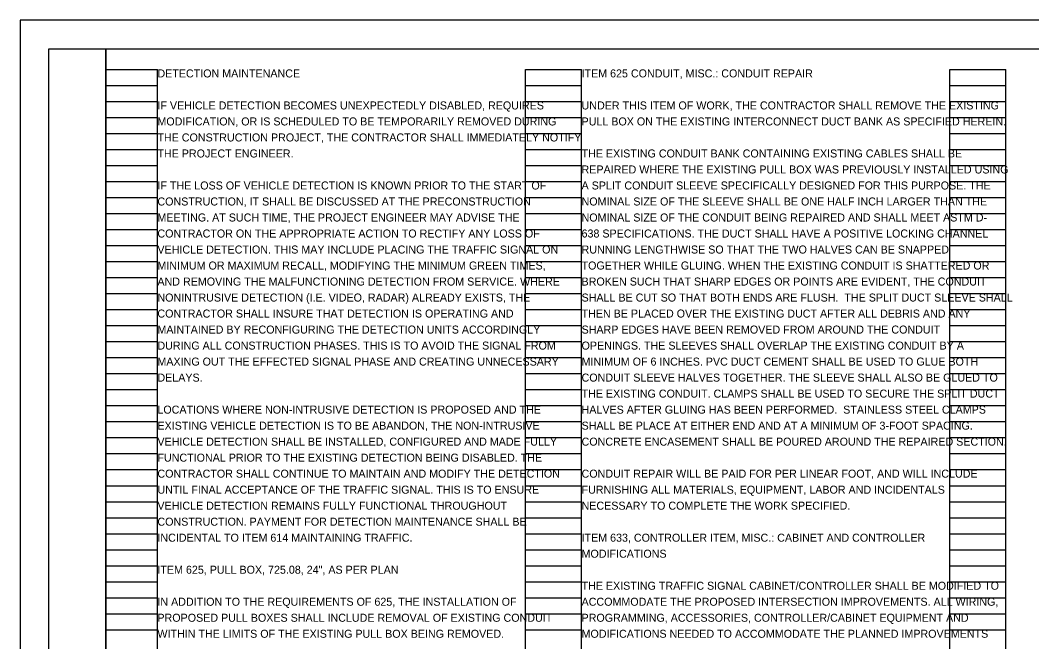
# Model space of a CAD drawing. Extents: x 0 to 34, y 0 to 22.
# Drawn here: x 0 to 17.7, y 11.13 to 22 of the extents above; entities that cross this region are included whole.
import ezdxf

# ---------------------------------------------------------------- set-up
doc = ezdxf.new("R2010")
doc.units = 0
for name, color, linetype in [('SH_Border', 7, 'Continuous'), ('SH_Cut_Line', 7, 'Continuous'), ('SH_Data', 7, 'Continuous'), ('SH_Text', 7, 'Continuous')]:
    doc.layers.add(name, color=color, linetype=linetype)

msp = doc.modelspace()

# ---------------------------------------------------------------- linework, layer by layer
at = {"layer": 'SH_Border'}
for points in [[(0.5, 21.5), (1.5, 21.5), (1.5, 0.5), (0.5, 0.5)], [(1.5, 21.5), (33.5, 21.5), (33.5, 0.5), (1.5, 0.5)]]:
    msp.add_lwpolyline(points, close=True, dxfattribs=at)
at = {"layer": 'SH_Cut_Line'}
msp.add_lwpolyline([(0, 0), (34, 0), (34, 22), (0, 22)], close=True, dxfattribs=at)
at = {"layer": 'SH_Data'}
for p, q in [((1.5, 0.98), (1.5, 21.14)), ((1.5, 21.14), (2.4, 21.14)), ((2.4, 0.98), (2.4, 21.14)), ((8.84, 0.98), (8.84, 21.14)), ((8.84, 21.14), (9.82, 21.14)), ((9.82, 0.98), (9.82, 21.14)), ((16.26, 0.98), (16.26, 21.14)), ((16.26, 21.14), (17.24, 21.14)), ((17.24, 0.98), (17.24, 21.14)), ((1.5, 20.86), (2.4, 20.86)), ((8.84, 20.86), (9.82, 20.86)), ((16.26, 20.86), (17.24, 20.86)), ((1.5, 20.58), (2.4, 20.58)), ((8.84, 20.58), (9.82, 20.58)), ((16.26, 20.58), (17.24, 20.58)), ((1.5, 20.3), (2.4, 20.3)), ((8.84, 20.3), (9.82, 20.3)), ((16.26, 20.3), (17.24, 20.3)), ((1.5, 20.02), (2.4, 20.02)), ((8.84, 20.02), (9.82, 20.02)), ((16.26, 20.02), (17.24, 20.02)), ((1.5, 19.74), (2.4, 19.74)), ((8.84, 19.74), (9.82, 19.74)), ((16.26, 19.74), (17.24, 19.74)), ((1.5, 19.46), (2.4, 19.46)), ((8.84, 19.46), (9.82, 19.46)), ((16.26, 19.46), (17.24, 19.46)), ((1.5, 19.18), (2.4, 19.18)), ((8.84, 19.18), (9.82, 19.18)), ((16.26, 19.18), (17.24, 19.18)), ((1.5, 18.9), (2.4, 18.9)), ((8.84, 18.9), (9.82, 18.9)), ((16.26, 18.9), (17.24, 18.9)), ((1.5, 18.62), (2.4, 18.62)), ((8.84, 18.62), (9.82, 18.62)), ((16.26, 18.62), (17.24, 18.62)), ((1.5, 18.34), (2.4, 18.34)), ((8.84, 18.34), (9.82, 18.34)), ((16.26, 18.34), (17.24, 18.34)), ((1.5, 18.06), (2.4, 18.06)), ((8.84, 18.06), (9.82, 18.06)), ((16.26, 18.06), (17.24, 18.06)), ((1.5, 17.78), (2.4, 17.78)), ((8.84, 17.78), (9.82, 17.78)), ((16.26, 17.78), (17.24, 17.78)), ((1.5, 17.5), (2.4, 17.5)), ((8.84, 17.5), (9.82, 17.5)), ((16.26, 17.5), (17.24, 17.5)), ((1.5, 17.22), (2.4, 17.22)), ((8.84, 17.22), (9.82, 17.22)), ((16.26, 17.22), (17.24, 17.22)), ((1.5, 16.94), (2.4, 16.94)), ((8.84, 16.94), (9.82, 16.94)), ((16.26, 16.94), (17.24, 16.94)), ((1.5, 16.66), (2.4, 16.66)), ((8.84, 16.66), (9.82, 16.66)), ((16.26, 16.66), (17.24, 16.66)), ((1.5, 16.38), (2.4, 16.38)), ((8.84, 16.38), (9.82, 16.38)), ((16.26, 16.38), (17.24, 16.38)), ((1.5, 16.1), (2.4, 16.1)), ((8.84, 16.1), (9.82, 16.1)), ((16.26, 16.1), (17.24, 16.1)), ((1.5, 15.82), (2.4, 15.82)), ((8.84, 15.82), (9.82, 15.82)), ((16.26, 15.82), (17.24, 15.82)), ((1.5, 15.54), (2.4, 15.54)), ((8.84, 15.54), (9.82, 15.54)), ((16.26, 15.54), (17.24, 15.54)), ((1.5, 15.26), (2.4, 15.26)), ((8.84, 15.26), (9.82, 15.26)), ((16.26, 15.26), (17.24, 15.26)), ((1.5, 14.98), (2.4, 14.98)), ((8.84, 14.98), (9.82, 14.98)), ((16.26, 14.98), (17.24, 14.98)), ((1.5, 14.7), (2.4, 14.7)), ((8.84, 14.7), (9.82, 14.7)), ((16.26, 14.7), (17.24, 14.7)), ((1.5, 14.42), (2.4, 14.42)), ((8.84, 14.42), (9.82, 14.42)), ((16.26, 14.42), (17.24, 14.42)), ((1.5, 14.14), (2.4, 14.14)), ((8.84, 14.14), (9.82, 14.14)), ((16.26, 14.14), (17.24, 14.14)), ((1.5, 13.86), (2.4, 13.86)), ((8.84, 13.86), (9.82, 13.86)), ((16.26, 13.86), (17.24, 13.86)), ((1.5, 13.58), (2.4, 13.58)), ((8.84, 13.58), (9.82, 13.58)), ((16.26, 13.58), (17.24, 13.58)), ((1.5, 13.3), (2.4, 13.3)), ((8.84, 13.3), (9.82, 13.3)), ((16.26, 13.3), (17.24, 13.3)), ((1.5, 13.02), (2.4, 13.02)), ((8.84, 13.02), (9.82, 13.02)), ((16.26, 13.02), (17.24, 13.02)), ((1.5, 12.74), (2.4, 12.74)), ((8.84, 12.74), (9.82, 12.74)), ((16.26, 12.74), (17.24, 12.74)), ((1.5, 12.46), (2.4, 12.46)), ((8.84, 12.46), (9.82, 12.46)), ((16.26, 12.46), (17.24, 12.46)), ((1.5, 12.18), (2.4, 12.18)), ((8.84, 12.18), (9.82, 12.18)), ((16.26, 12.18), (17.24, 12.18)), ((1.5, 11.9), (2.4, 11.9)), ((8.84, 11.9), (9.82, 11.9)), ((16.26, 11.9), (17.24, 11.9)), ((1.5, 11.62), (2.4, 11.62)), ((8.84, 11.62), (9.82, 11.62)), ((16.26, 11.62), (17.24, 11.62)), ((1.5, 11.34), (2.4, 11.34)), ((8.84, 11.34), (9.82, 11.34)), ((16.26, 11.34), (17.24, 11.34))]:
    msp.add_line(p, q, dxfattribs=at)

# ---------------------------------------------------------------- texts
at = {"layer": 'SH_Text'}
for s, p in [('DETECTION MAINTENANCE', (2.4, 21)), ('ITEM 625 CONDUIT, MISC.: CONDUIT REPAIR', (9.82, 21)), ('IF VEHICLE DETECTION BECOMES UNEXPECTEDLY DISABLED, REQUIRES ', (2.4, 20.44)), ('UNDER THIS ITEM OF WORK, THE CONTRACTOR SHALL REMOVE THE EXISTING ', (9.82, 20.44)), ('MODIFICATION, OR IS SCHEDULED TO BE TEMPORARILY REMOVED DURING ', (2.4, 20.16)), ('PULL BOX ON THE EXISTING INTERCONNECT DUCT BANK AS SPECIFIED HEREIN.', (9.82, 20.16)), ('THE CONSTRUCTION PROJECT, THE CONTRACTOR SHALL IMMEDIATELY NOTIFY ', (2.4, 19.88)), ('THE PROJECT ENGINEER.', (2.4, 19.6)), ('THE EXISTING CONDUIT BANK CONTAINING EXISTING CABLES SHALL BE ', (9.82, 19.6)), ('REPAIRED WHERE THE EXISTING PULL BOX WAS PREVIOUSLY INSTALLED USING ', (9.82, 19.32)), ('IF THE LOSS OF VEHICLE DETECTION IS KNOWN PRIOR TO THE START OF ', (2.4, 19.04)), ('A SPLIT CONDUIT SLEEVE SPECIFICALLY DESIGNED FOR THIS PURPOSE. THE ', (9.82, 19.04)), ('CONSTRUCTION, IT SHALL BE DISCUSSED AT THE PRECONSTRUCTION ', (2.4, 18.76)), ('NOMINAL SIZE OF THE SLEEVE SHALL BE ONE HALF INCH LARGER THAN THE ', (9.82, 18.76)), ('MEETING. AT SUCH TIME, THE PROJECT ENGINEER MAY ADVISE THE ', (2.4, 18.48)), ('NOMINAL SIZE OF THE CONDUIT BEING REPAIRED AND SHALL MEET ASTM D-', (9.82, 18.48)), ('CONTRACTOR ON THE APPROPRIATE ACTION TO RECTIFY ANY LOSS OF ', (2.4, 18.2)), ('638 SPECIFICATIONS. THE DUCT SHALL HAVE A POSITIVE LOCKING CHANNEL ', (9.82, 18.2)), ('VEHICLE DETECTION. THIS MAY INCLUDE PLACING THE TRAFFIC SIGNAL ON ', (2.4, 17.92)), ('RUNNING LENGTHWISE SO THAT THE TWO HALVES CAN BE SNAPPED ', (9.82, 17.92)), ('MINIMUM OR MAXIMUM RECALL, MODIFYING THE MINIMUM GREEN TIMES, ', (2.4, 17.64)), ('TOGETHER WHILE GLUING. WHEN THE EXISTING CONDUIT IS SHATTERED OR ', (9.82, 17.64)), ('AND REMOVING THE MALFUNCTIONING DETECTION FROM SERVICE. WHERE ', (2.4, 17.36)), ('BROKEN SUCH THAT SHARP EDGES OR POINTS ARE EVIDENT, THE CONDUIT ', (9.82, 17.36)), ('NONINTRUSIVE DETECTION (I.E. VIDEO, RADAR) ALREADY EXISTS, THE ', (2.4, 17.08)), ('SHALL BE CUT SO THAT BOTH ENDS ARE FLUSH.  THE SPLIT DUCT SLEEVE SHALL ', (9.82, 17.08)), ('CONTRACTOR SHALL INSURE THAT DETECTION IS OPERATING AND ', (2.4, 16.8)), ('THEN BE PLACED OVER THE EXISTING DUCT AFTER ALL DEBRIS AND ANY ', (9.82, 16.8)), ('MAINTAINED BY RECONFIGURING THE DETECTION UNITS ACCORDINGLY ', (2.4, 16.52)), ('SHARP EDGES HAVE BEEN REMOVED FROM AROUND THE CONDUIT ', (9.82, 16.52)), ('DURING ALL CONSTRUCTION PHASES. THIS IS TO AVOID THE SIGNAL FROM ', (2.4, 16.24)), ('OPENINGS. THE SLEEVES SHALL OVERLAP THE EXISTING CONDUIT BY A ', (9.82, 16.24)), ('MAXING OUT THE EFFECTED SIGNAL PHASE AND CREATING UNNECESSARY ', (2.4, 15.96)), ('MINIMUM OF 6 INCHES. PVC DUCT CEMENT SHALL BE USED TO GLUE BOTH ', (9.82, 15.96)), ('DELAYS.', (2.4, 15.68)), ('CONDUIT SLEEVE HALVES TOGETHER. THE SLEEVE SHALL ALSO BE GLUED TO ', (9.82, 15.68)), ('THE EXISTING CONDUIT. CLAMPS SHALL BE USED TO SECURE THE SPLIT DUCT ', (9.82, 15.4)), ('LOCATIONS WHERE NON-INTRUSIVE DETECTION IS PROPOSED AND THE ', (2.4, 15.12)), ('HALVES AFTER GLUING HAS BEEN PERFORMED.  STAINLESS STEEL CLAMPS ', (9.82, 15.12)), ('EXISTING VEHICLE DETECTION IS TO BE ABANDON, THE NON-INTRUSIVE ', (2.4, 14.84)), ('SHALL BE PLACE AT EITHER END AND AT A MINIMUM OF 3-FOOT SPACING. ', (9.82, 14.84)), ('VEHICLE DETECTION SHALL BE INSTALLED, CONFIGURED AND MADE FULLY ', (2.4, 14.56)), ('CONCRETE ENCASEMENT SHALL BE POURED AROUND THE REPAIRED SECTION. ', (9.82, 14.56)), ('FUNCTIONAL PRIOR TO THE EXISTING DETECTION BEING DISABLED. THE ', (2.4, 14.28)), ('CONTRACTOR SHALL CONTINUE TO MAINTAIN AND MODIFY THE DETECTION ', (2.4, 14)), ('CONDUIT REPAIR WILL BE PAID FOR PER LINEAR FOOT, AND WILL INCLUDE ', (9.82, 14)), ('UNTIL FINAL ACCEPTANCE OF THE TRAFFIC SIGNAL. THIS IS TO ENSURE ', (2.4, 13.72)), ('FURNISHING ALL MATERIALS, EQUIPMENT, LABOR AND INCIDENTALS ', (9.82, 13.72)), ('VEHICLE DETECTION REMAINS FULLY FUNCTIONAL THROUGHOUT ', (2.4, 13.44)), ('NECESSARY TO COMPLETE THE WORK SPECIFIED.', (9.82, 13.44)), ('CONSTRUCTION. PAYMENT FOR DETECTION MAINTENANCE SHALL BE ', (2.4, 13.16)), ('INCIDENTAL TO ITEM 614 MAINTAINING TRAFFIC.', (2.4, 12.88)), ('ITEM 633, CONTROLLER ITEM, MISC.: CABINET AND CONTROLLER ', (9.82, 12.88)), ('MODIFICATIONS', (9.82, 12.6)), ('ITEM 625, PULL BOX, 725.08, 24", AS PER PLAN', (2.4, 12.32)), ('THE EXISTING TRAFFIC SIGNAL CABINET/CONTROLLER SHALL BE MODIFIED TO ', (9.82, 12.04)), ('IN ADDITION TO THE REQUIREMENTS OF 625, THE INSTALLATION OF ', (2.4, 11.76)), ('ACCOMMODATE THE PROPOSED INTERSECTION IMPROVEMENTS. ALL WIRING, ', (9.82, 11.76)), ('PROPOSED PULL BOXES SHALL INCLUDE REMOVAL OF EXISTING CONDUIT ', (2.4, 11.48)), ('PROGRAMMING, ACCESSORIES, CONTROLLER/CABINET EQUIPMENT AND ', (9.82, 11.48)), ('WITHIN THE LIMITS OF THE EXISTING PULL BOX BEING REMOVED.', (2.4, 11.2)), ('MODIFICATIONS NEEDED TO ACCOMMODATE THE PLANNED IMPROVEMENTS ', (9.82, 11.2))]:
    msp.add_text(s, height=0.14, dxfattribs=at).set_placement(p)

doc.saveas('drawing.dxf')
